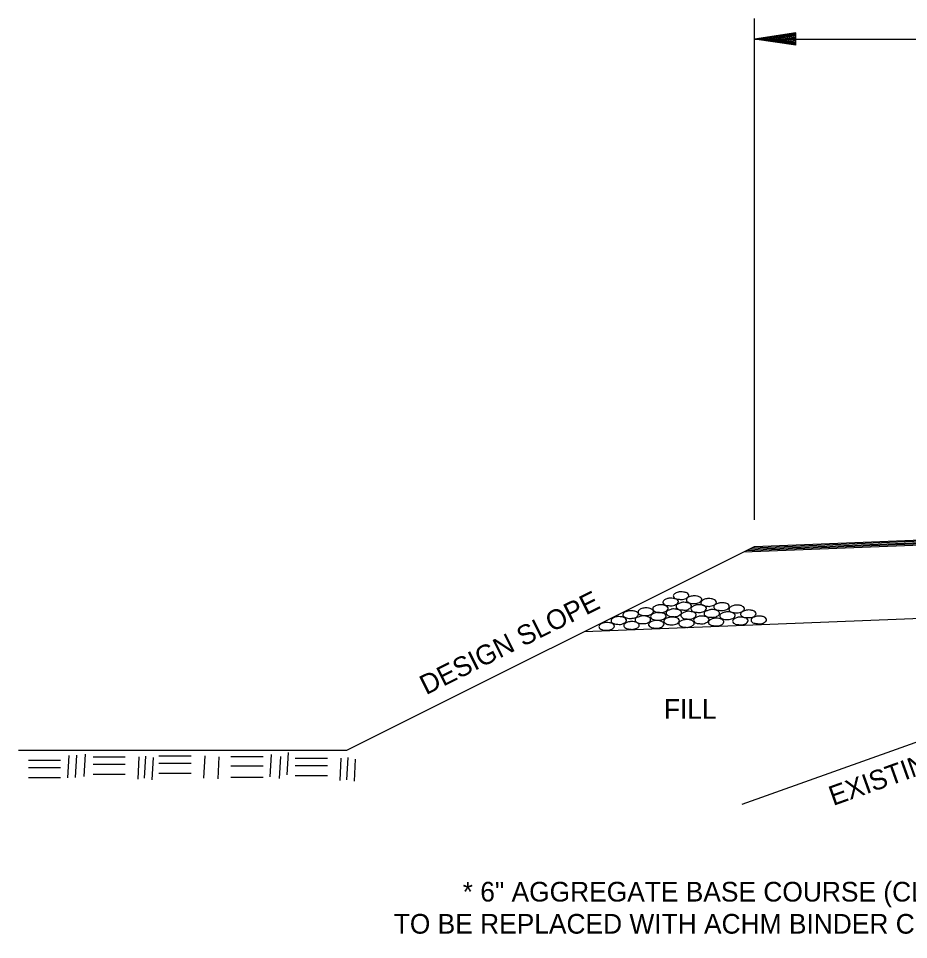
# Model space of a CAD drawing. Extents: x 1955771 to 1955918, y 566326 to 566544.
# Drawn here: x 1955777.06 to 1955804.18, y 566459.62 to 566487.69 of the extents above; entities that cross this region are included whole.
import ezdxf

# ---------------------------------------------------------------- set-up
doc = ezdxf.new("R2010")
doc.units = 0
doc.layers.add('R_Logo', color=7, linetype='Continuous')

msp = doc.modelspace()

# ---------------------------------------------------------------- linework, layer by layer
at = {"layer": 'R_Logo'}
for p, q in [((1955799.49, 566472.41), (1955799.49, 566487.691)), ((1955800.749, 566487.249), (1955799.49, 566487.062)), ((1955800.749, 566487.221), (1955799.699, 566487.062)), ((1955800.749, 566487.188), (1955799.915, 566487.062)), ((1955800.749, 566487.156), (1955800.126, 566487.062)), ((1955800.749, 566487.124), (1955800.338, 566487.062)), ((1955800.749, 566487.092), (1955800.549, 566487.062)), ((1955800.749, 566486.872), (1955800.749, 566487.249)), ((1955799.49, 566487.062), (1955863.596, 566487.062)), ((1955800.749, 566486.872), (1955799.49, 566487.062)), ((1955800.749, 566486.905), (1955799.699, 566487.062)), ((1955800.749, 566486.937), (1955799.915, 566487.062)), ((1955800.749, 566486.968), (1955800.126, 566487.062)), ((1955800.749, 566487.003), (1955800.338, 566487.062)), ((1955800.749, 566487.032), (1955800.549, 566487.062)), ((1955799.49, 566471.595), (1955863.6, 566474.157)), ((1955799.162, 566471.432), (1955863.887, 566474.014)), ((1955799.246, 566471.475), (1955863.815, 566474.05)), ((1955799.33, 566471.515), (1955863.744, 566474.086)), ((1955799.415, 566471.56), (1955863.668, 566474.123)), ((1955787.072, 566465.391), (1955799.49, 566471.595)), ((1955794.305, 566469.004), (1955819.421, 566470.005)), ((1955813.869, 566469.01), (1955799.104, 566463.734)), ((1955777.063, 566465.391), (1955787.072, 566465.391)), ((1955778.601, 566465.224), (1955778.562, 566464.547)), ((1955778.833, 566465.24), (1955778.796, 566464.56)), ((1955779.093, 566465.264), (1955779.052, 566464.588)), ((1955779.339, 566465.188), (1955780.319, 566465.188)), ((1955780.731, 566465.188), (1955780.696, 566464.511)), ((1955780.936, 566465.211), (1955780.897, 566464.537)), ((1955781.343, 566465.218), (1955782.324, 566465.218)), ((1955782.737, 566465.218), (1955782.699, 566464.542)), ((1955783.171, 566465.192), (1955783.134, 566464.518)), ((1955783.536, 566465.202), (1955784.516, 566465.202)), ((1955784.758, 566465.259), (1955784.718, 566464.582)), ((1955785.048, 566465.2), (1955785.008, 566464.527)), ((1955785.278, 566465.319), (1955785.238, 566464.638)), ((1955777.366, 566465.087), (1955778.343, 566465.087)), ((1955779.339, 566464.964), (1955780.319, 566464.964)), ((1955781.168, 566465.166), (1955781.131, 566464.487)), ((1955781.343, 566464.993), (1955782.324, 566464.993)), ((1955783.536, 566464.913), (1955784.516, 566464.913)), ((1955785.497, 566465.145), (1955786.478, 566465.145)), ((1955785.497, 566464.92), (1955786.478, 566464.92)), ((1955786.889, 566465.145), (1955786.854, 566464.468)), ((1955787.094, 566465.169), (1955787.056, 566464.489)), ((1955787.326, 566465.12), (1955787.286, 566464.444)), ((1955777.366, 566464.862), (1955778.343, 566464.862)), ((1955779.339, 566464.663), (1955780.319, 566464.663)), ((1955781.343, 566464.692), (1955782.324, 566464.692)), ((1955785.497, 566464.617), (1955786.478, 566464.617)), ((1955777.366, 566464.557), (1955778.343, 566464.557)), ((1955783.536, 566464.565), (1955784.516, 566464.565))]:
    msp.add_line(p, q, dxfattribs=at)
for points in [[(1955796.926, 566470.026), (1955797.011, 566470.015), (1955797.107, 566469.991), (1955797.16, 566469.944), (1955797.168, 566469.915), (1955797.142, 566469.864), (1955797.111, 566469.842), (1955797.055, 566469.812), (1955796.975, 566469.79), (1955796.935, 566469.79), (1955796.873, 566469.797), (1955796.803, 566469.801), (1955796.751, 566469.823), (1955796.704, 566469.868), (1955796.695, 566469.9), (1955796.712, 566469.945), (1955796.749, 566469.977), (1955796.785, 566469.994), (1955796.84, 566470.011), (1955796.873, 566470.023), (1955796.926, 566470.026)], [(1955797.242, 566470.219), (1955797.325, 566470.21), (1955797.424, 566470.182), (1955797.477, 566470.138), (1955797.485, 566470.108), (1955797.46, 566470.058), (1955797.427, 566470.034), (1955797.371, 566470.003), (1955797.293, 566469.983), (1955797.25, 566469.983), (1955797.19, 566469.99), (1955797.118, 566469.994), (1955797.069, 566470.015), (1955797.02, 566470.061), (1955797.013, 566470.092), (1955797.028, 566470.138), (1955797.064, 566470.168), (1955797.1, 566470.185), (1955797.156, 566470.203), (1955797.188, 566470.217), (1955797.242, 566470.219)], [(1955797.642, 566470.095), (1955797.727, 566470.088), (1955797.825, 566470.056), (1955797.874, 566470.013), (1955797.881, 566469.988), (1955797.856, 566469.933), (1955797.833, 566469.907), (1955797.774, 566469.879), (1955797.697, 566469.863), (1955797.655, 566469.86), (1955797.592, 566469.862), (1955797.521, 566469.873), (1955797.471, 566469.897), (1955797.418, 566469.936), (1955797.41, 566469.969), (1955797.425, 566470.013), (1955797.465, 566470.049), (1955797.499, 566470.066), (1955797.557, 566470.081), (1955797.591, 566470.088), (1955797.642, 566470.095)], [(1955798.083, 566470.009), (1955798.166, 566470.007), (1955798.268, 566469.974), (1955798.315, 566469.926), (1955798.324, 566469.897), (1955798.297, 566469.846), (1955798.27, 566469.823), (1955798.215, 566469.799), (1955798.134, 566469.776), (1955798.091, 566469.773), (1955798.029, 566469.778), (1955797.962, 566469.79), (1955797.909, 566469.811), (1955797.86, 566469.85), (1955797.852, 566469.881), (1955797.868, 566469.927), (1955797.905, 566469.956), (1955797.94, 566469.983), (1955797.996, 566470), (1955798.031, 566470.007), (1955798.083, 566470.009)], [(1955796.17, 566469.726), (1955796.255, 566469.72), (1955796.352, 566469.69), (1955796.401, 566469.643), (1955796.407, 566469.614), (1955796.382, 566469.565), (1955796.356, 566469.541), (1955796.301, 566469.512), (1955796.221, 566469.491), (1955796.179, 566469.491), (1955796.117, 566469.497), (1955796.05, 566469.503), (1955795.996, 566469.523), (1955795.944, 566469.567), (1955795.937, 566469.6), (1955795.951, 566469.644), (1955795.988, 566469.674), (1955796.026, 566469.696), (1955796.085, 566469.715), (1955796.117, 566469.723), (1955796.17, 566469.726)], [(1955796.618, 566469.823), (1955796.701, 566469.815), (1955796.798, 566469.784), (1955796.849, 566469.743), (1955796.856, 566469.712), (1955796.829, 566469.663), (1955796.8, 566469.635), (1955796.749, 566469.605), (1955796.669, 566469.588), (1955796.627, 566469.588), (1955796.563, 566469.587), (1955796.494, 566469.598), (1955796.441, 566469.622), (1955796.391, 566469.667), (1955796.385, 566469.694), (1955796.4, 566469.745), (1955796.436, 566469.773), (1955796.474, 566469.79), (1955796.533, 566469.808), (1955796.563, 566469.818), (1955796.618, 566469.823)], [(1955797.021, 566469.694), (1955797.105, 566469.686), (1955797.206, 566469.656), (1955797.257, 566469.611), (1955797.266, 566469.584), (1955797.239, 566469.532), (1955797.211, 566469.51), (1955797.152, 566469.476), (1955797.076, 566469.459), (1955797.033, 566469.459), (1955796.969, 566469.461), (1955796.901, 566469.468), (1955796.849, 566469.495), (1955796.8, 566469.536), (1955796.792, 566469.569), (1955796.809, 566469.614), (1955796.847, 566469.644), (1955796.882, 566469.661), (1955796.935, 566469.677), (1955796.969, 566469.69), (1955797.021, 566469.694)], [(1955797.328, 566469.896), (1955797.41, 566469.886), (1955797.511, 566469.862), (1955797.559, 566469.813), (1955797.566, 566469.786), (1955797.542, 566469.734), (1955797.512, 566469.711), (1955797.46, 566469.681), (1955797.38, 566469.661), (1955797.338, 566469.661), (1955797.274, 566469.667), (1955797.205, 566469.67), (1955797.154, 566469.694), (1955797.104, 566469.739), (1955797.095, 566469.77), (1955797.11, 566469.817), (1955797.149, 566469.845), (1955797.186, 566469.862), (1955797.242, 566469.883), (1955797.274, 566469.894), (1955797.328, 566469.896)], [(1955797.782, 566469.821), (1955797.865, 566469.818), (1955797.967, 566469.787), (1955798.014, 566469.74), (1955798.021, 566469.711), (1955797.996, 566469.66), (1955797.972, 566469.637), (1955797.913, 566469.609), (1955797.836, 566469.587), (1955797.793, 566469.587), (1955797.728, 566469.591), (1955797.661, 566469.602), (1955797.609, 566469.621), (1955797.558, 566469.664), (1955797.551, 566469.696), (1955797.564, 566469.743), (1955797.604, 566469.771), (1955797.64, 566469.791), (1955797.696, 566469.813), (1955797.728, 566469.821), (1955797.782, 566469.821)], [(1955798.185, 566469.675), (1955798.27, 566469.668), (1955798.365, 566469.637), (1955798.414, 566469.592), (1955798.421, 566469.567), (1955798.398, 566469.512), (1955798.37, 566469.488), (1955798.314, 566469.457), (1955798.234, 566469.439), (1955798.193, 566469.439), (1955798.132, 566469.44), (1955798.062, 566469.448), (1955798.009, 566469.474), (1955797.956, 566469.516), (1955797.948, 566469.551), (1955797.965, 566469.595), (1955798.002, 566469.626), (1955798.04, 566469.641), (1955798.095, 566469.66), (1955798.134, 566469.671), (1955798.185, 566469.675)], [(1955798.48, 566469.88), (1955798.565, 566469.876), (1955798.662, 566469.845), (1955798.71, 566469.799), (1955798.719, 566469.768), (1955798.692, 566469.719), (1955798.67, 566469.696), (1955798.611, 566469.67), (1955798.531, 566469.644), (1955798.49, 566469.644), (1955798.428, 566469.65), (1955798.362, 566469.658), (1955798.305, 566469.677), (1955798.253, 566469.722), (1955798.246, 566469.753), (1955798.261, 566469.8), (1955798.298, 566469.829), (1955798.337, 566469.85), (1955798.393, 566469.872), (1955798.428, 566469.877), (1955798.48, 566469.88)], [(1955798.943, 566469.81), (1955799.026, 566469.808), (1955799.123, 566469.773), (1955799.171, 566469.73), (1955799.179, 566469.701), (1955799.156, 566469.647), (1955799.127, 566469.625), (1955799.073, 566469.598), (1955798.992, 566469.576), (1955798.951, 566469.572), (1955798.89, 566469.579), (1955798.82, 566469.589), (1955798.766, 566469.609), (1955798.716, 566469.65), (1955798.708, 566469.682), (1955798.724, 566469.728), (1955798.76, 566469.761), (1955798.799, 566469.783), (1955798.855, 566469.8), (1955798.89, 566469.808), (1955798.943, 566469.81)], [(1955795.349, 566469.459), (1955795.431, 566469.454), (1955795.531, 566469.425), (1955795.58, 566469.376), (1955795.587, 566469.349), (1955795.563, 566469.296), (1955795.536, 566469.274), (1955795.48, 566469.25), (1955795.402, 566469.224), (1955795.359, 566469.224), (1955795.294, 566469.228), (1955795.226, 566469.241), (1955795.174, 566469.258), (1955795.124, 566469.3), (1955795.117, 566469.334), (1955795.131, 566469.379), (1955795.171, 566469.409), (1955795.208, 566469.431), (1955795.263, 566469.449), (1955795.294, 566469.457), (1955795.349, 566469.459)], [(1955795.71, 566469.641), (1955795.793, 566469.637), (1955795.89, 566469.602), (1955795.942, 566469.562), (1955795.95, 566469.535), (1955795.921, 566469.48), (1955795.897, 566469.453), (1955795.839, 566469.428), (1955795.763, 566469.41), (1955795.722, 566469.406), (1955795.656, 566469.407), (1955795.585, 566469.42), (1955795.535, 566469.444), (1955795.485, 566469.483), (1955795.478, 566469.514), (1955795.493, 566469.562), (1955795.53, 566469.595), (1955795.568, 566469.611), (1955795.624, 566469.63), (1955795.655, 566469.637), (1955795.71, 566469.641)], [(1955796.088, 566469.483), (1955796.169, 566469.474), (1955796.264, 566469.444), (1955796.314, 566469.401), (1955796.321, 566469.372), (1955796.298, 566469.321), (1955796.271, 566469.293), (1955796.216, 566469.265), (1955796.134, 566469.25), (1955796.093, 566469.25), (1955796.029, 566469.25), (1955795.96, 566469.257), (1955795.907, 566469.281), (1955795.858, 566469.326), (1955795.848, 566469.358), (1955795.865, 566469.404), (1955795.901, 566469.432), (1955795.941, 566469.448), (1955795.996, 566469.466), (1955796.031, 566469.478), (1955796.088, 566469.483)], [(1955796.554, 566469.585), (1955796.635, 566469.58), (1955796.736, 566469.551), (1955796.786, 566469.503), (1955796.792, 566469.474), (1955796.767, 566469.424), (1955796.742, 566469.401), (1955796.684, 566469.373), (1955796.607, 566469.351), (1955796.562, 566469.351), (1955796.499, 566469.355), (1955796.43, 566469.364), (1955796.379, 566469.384), (1955796.328, 566469.428), (1955796.321, 566469.459), (1955796.336, 566469.505), (1955796.374, 566469.535), (1955796.411, 566469.555), (1955796.466, 566469.576), (1955796.499, 566469.584), (1955796.554, 566469.585)], [(1955796.963, 566469.448), (1955797.045, 566469.439), (1955797.142, 566469.41), (1955797.19, 566469.365), (1955797.198, 566469.338), (1955797.175, 566469.288), (1955797.149, 566469.26), (1955797.092, 566469.23), (1955797.012, 566469.213), (1955796.969, 566469.213), (1955796.906, 566469.215), (1955796.84, 566469.223), (1955796.786, 566469.25), (1955796.733, 566469.29), (1955796.725, 566469.325), (1955796.742, 566469.368), (1955796.781, 566469.399), (1955796.817, 566469.416), (1955796.873, 566469.432), (1955796.909, 566469.444), (1955796.963, 566469.448)], [(1955797.475, 566469.622), (1955797.558, 566469.611), (1955797.655, 566469.585), (1955797.704, 566469.538), (1955797.711, 566469.51), (1955797.685, 566469.459), (1955797.661, 566469.436), (1955797.604, 566469.406), (1955797.526, 566469.385), (1955797.482, 566469.385), (1955797.421, 566469.389), (1955797.35, 566469.395), (1955797.296, 566469.42), (1955797.248, 566469.464), (1955797.24, 566469.496), (1955797.253, 566469.54), (1955797.291, 566469.57), (1955797.33, 566469.588), (1955797.388, 566469.607), (1955797.421, 566469.619), (1955797.475, 566469.622)], [(1955797.866, 566469.478), (1955797.95, 566469.471), (1955798.048, 566469.439), (1955798.095, 566469.394), (1955798.103, 566469.364), (1955798.077, 566469.315), (1955798.055, 566469.292), (1955797.998, 566469.266), (1955797.918, 566469.241), (1955797.875, 566469.241), (1955797.812, 566469.248), (1955797.744, 566469.255), (1955797.692, 566469.274), (1955797.638, 566469.319), (1955797.632, 566469.351), (1955797.647, 566469.395), (1955797.685, 566469.427), (1955797.723, 566469.445), (1955797.779, 566469.466), (1955797.812, 566469.474), (1955797.866, 566469.478)], [(1955798.313, 566469.41), (1955798.397, 566469.406), (1955798.497, 566469.375), (1955798.546, 566469.327), (1955798.554, 566469.299), (1955798.528, 566469.25), (1955798.504, 566469.225), (1955798.446, 566469.197), (1955798.368, 566469.177), (1955798.325, 566469.177), (1955798.261, 566469.181), (1955798.192, 566469.191), (1955798.141, 566469.208), (1955798.089, 566469.253), (1955798.082, 566469.284), (1955798.097, 566469.329), (1955798.137, 566469.36), (1955798.172, 566469.38), (1955798.227, 566469.402), (1955798.261, 566469.409), (1955798.313, 566469.41)], [(1955798.661, 566469.605), (1955798.743, 566469.601), (1955798.843, 566469.567), (1955798.891, 566469.525), (1955798.899, 566469.499), (1955798.873, 566469.442), (1955798.849, 566469.418), (1955798.79, 566469.391), (1955798.713, 566469.373), (1955798.671, 566469.369), (1955798.608, 566469.37), (1955798.537, 566469.383), (1955798.487, 566469.407), (1955798.437, 566469.445), (1955798.428, 566469.48), (1955798.443, 566469.525), (1955798.48, 566469.559), (1955798.519, 566469.575), (1955798.574, 566469.592), (1955798.607, 566469.601), (1955798.661, 566469.605)], [(1955799.047, 566469.445), (1955799.135, 566469.436), (1955799.232, 566469.411), (1955799.284, 566469.364), (1955799.292, 566469.337), (1955799.267, 566469.284), (1955799.238, 566469.262), (1955799.178, 566469.23), (1955799.102, 566469.211), (1955799.06, 566469.211), (1955798.997, 566469.216), (1955798.926, 566469.22), (1955798.875, 566469.246), (1955798.827, 566469.289), (1955798.819, 566469.321), (1955798.835, 566469.365), (1955798.872, 566469.396), (1955798.907, 566469.413), (1955798.964, 566469.432), (1955798.996, 566469.445), (1955799.047, 566469.445)], [(1955799.299, 566469.664), (1955799.381, 566469.655), (1955799.478, 566469.625), (1955799.526, 566469.58), (1955799.533, 566469.553), (1955799.51, 566469.501), (1955799.484, 566469.474), (1955799.427, 566469.444), (1955799.346, 566469.429), (1955799.305, 566469.429), (1955799.244, 566469.431), (1955799.174, 566469.436), (1955799.119, 566469.462), (1955799.068, 566469.505), (1955799.062, 566469.537), (1955799.076, 566469.583), (1955799.115, 566469.613), (1955799.153, 566469.63), (1955799.208, 566469.647), (1955799.246, 566469.658), (1955799.299, 566469.664)], [(1955799.616, 566469.476), (1955799.699, 566469.474), (1955799.796, 566469.438), (1955799.844, 566469.396), (1955799.853, 566469.367), (1955799.829, 566469.313), (1955799.8, 566469.29), (1955799.749, 566469.265), (1955799.665, 566469.244), (1955799.625, 566469.241), (1955799.563, 566469.246), (1955799.493, 566469.257), (1955799.439, 566469.275), (1955799.389, 566469.317), (1955799.381, 566469.349), (1955799.397, 566469.394), (1955799.433, 566469.429), (1955799.473, 566469.448), (1955799.529, 566469.466), (1955799.564, 566469.474), (1955799.616, 566469.476)], [(1955794.979, 566469.281), (1955795.067, 566469.274), (1955795.163, 566469.246), (1955795.21, 566469.197), (1955795.218, 566469.171), (1955795.193, 566469.119), (1955795.169, 566469.097), (1955795.112, 566469.07), (1955795.032, 566469.045), (1955794.99, 566469.045), (1955794.927, 566469.05), (1955794.86, 566469.058), (1955794.807, 566469.08), (1955794.756, 566469.122), (1955794.748, 566469.155), (1955794.764, 566469.199), (1955794.799, 566469.23), (1955794.837, 566469.253), (1955794.895, 566469.271), (1955794.927, 566469.278), (1955794.979, 566469.281)], [(1955795.739, 566469.309), (1955795.823, 566469.306), (1955795.92, 566469.271), (1955795.967, 566469.228), (1955795.976, 566469.199), (1955795.951, 566469.145), (1955795.924, 566469.122), (1955795.872, 566469.097), (1955795.79, 566469.076), (1955795.747, 566469.071), (1955795.685, 566469.079), (1955795.618, 566469.09), (1955795.563, 566469.112), (1955795.511, 566469.15), (1955795.504, 566469.182), (1955795.518, 566469.227), (1955795.558, 566469.26), (1955795.594, 566469.281), (1955795.649, 566469.297), (1955795.687, 566469.306), (1955795.739, 566469.309)], [(1955796.491, 566469.344), (1955796.575, 566469.338), (1955796.677, 566469.305), (1955796.724, 566469.263), (1955796.73, 566469.238), (1955796.706, 566469.182), (1955796.682, 566469.155), (1955796.622, 566469.127), (1955796.545, 566469.113), (1955796.503, 566469.11), (1955796.441, 566469.112), (1955796.369, 566469.121), (1955796.318, 566469.145), (1955796.267, 566469.186), (1955796.259, 566469.217), (1955796.275, 566469.263), (1955796.313, 566469.296), (1955796.351, 566469.313), (1955796.404, 566469.33), (1955796.439, 566469.338), (1955796.491, 566469.344)], [(1955797.414, 566469.369), (1955797.494, 566469.367), (1955797.596, 566469.334), (1955797.642, 566469.29), (1955797.651, 566469.262), (1955797.627, 566469.207), (1955797.599, 566469.186), (1955797.547, 566469.16), (1955797.465, 566469.135), (1955797.422, 566469.131), (1955797.359, 566469.139), (1955797.291, 566469.151), (1955797.237, 566469.173), (1955797.186, 566469.211), (1955797.178, 566469.244), (1955797.194, 566469.289), (1955797.233, 566469.323), (1955797.27, 566469.344), (1955797.326, 566469.36), (1955797.359, 566469.367), (1955797.414, 566469.369)]]:
    msp.add_spline(points, degree=3, dxfattribs=at)

# ---------------------------------------------------------------- texts
for s, rotation, p in [('DESIGN SLOPE', 26.565, (1955789.483, 566467.062)), ('EXISTING SLOPE', 19.6609, (1955801.883, 566463.688))]:
    msp.add_text(s, height=0.6, rotation=rotation, dxfattribs=at).set_placement(p)
for s, p in [('FILL', (1955796.726, 566466.346)), ('* 6" AGGREGATE BASE COURSE (CLASS 7)', (1955790.597, 566460.777)), ('TO BE REPLACED WITH ACHM BINDER COURSE (1")', (1955788.497, 566459.799))]:
    msp.add_text(s, height=0.6, dxfattribs=at).set_placement(p)

doc.saveas('drawing.dxf')
